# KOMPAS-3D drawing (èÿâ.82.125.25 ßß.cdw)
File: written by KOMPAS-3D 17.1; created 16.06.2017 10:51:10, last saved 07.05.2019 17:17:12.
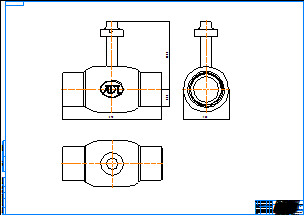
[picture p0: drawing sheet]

Sheet 1: A0, landscape

Title block, sheet 1: name: КШГ.82.125.25 сс; material: Внимание! Данный продукт является объектом авторского права ООО «Торговый Дом АДЛ». / Запрещается изменение, копирование, распространение / (в том числе путем копирования на другие сайты и ресурсы в Интернете) / или любое иное использование информации и объектов без предварительного / согласия правообладателя (ООО «Торговый Дом АДЛ»).; scale: 1:1; sheets: 1; organisation: ООО "Торговый дом АДЛ"; sheet format: A0; stored path: C:\Users\tra\Desktop\2д чертежи\Шаровые краны БИВАЛ\КШ_Бивал_серия_82_85\KOMPAS 2D\КШГ.82.125.25 сс.cdw

Views: Спереди 1, Проекционный вид 2, Проекционный вид 3
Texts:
  Klimkovich
  ADL
Dimensions and other numbers on the sheet: 390; 266,9; 66,5; 180; 1:1; 1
